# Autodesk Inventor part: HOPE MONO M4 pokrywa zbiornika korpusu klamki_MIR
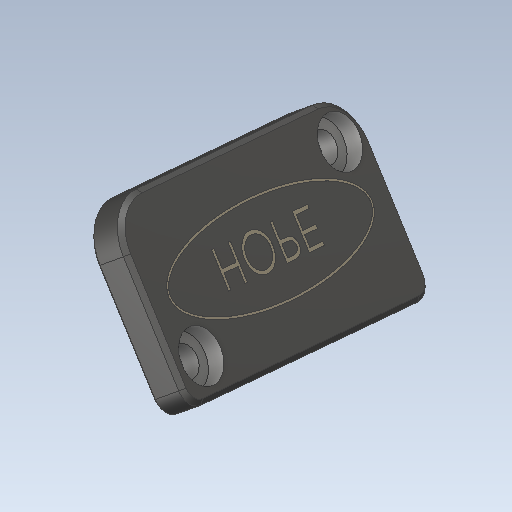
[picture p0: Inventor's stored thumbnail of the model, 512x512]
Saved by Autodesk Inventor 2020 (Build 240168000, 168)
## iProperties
Created: 2015-11
Part Number: HOPE MONO M4 pokrywa zbiornika korpusu klamki_MIR
Material: Ogólny
Document SubType Name: Modeling
Designer: Tomasz
Density: 1 g/cm^3
Appearance: Domyślna
Sending System: SolidWorks 2017
Last Author: Tomasz
Last Saved: 2017-10-01
Author: Tomasz
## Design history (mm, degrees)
feature "Imported1"
node "Bryła1"
